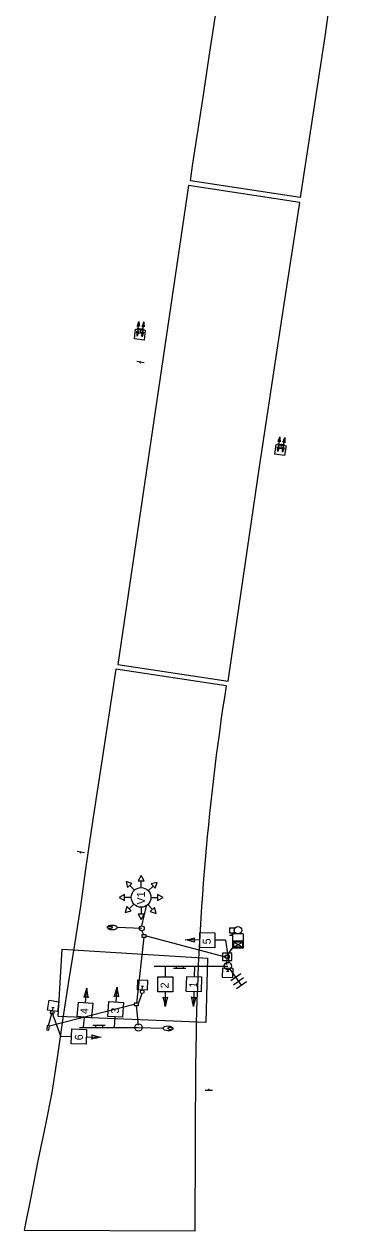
# Model space of a CAD drawing. Extents: x 991933 to 997296, y 1973751 to 1976728.
# Drawn here: x 991933.1 to 992072.6, y 1975023.7 to 1975513.6 of the extents above; entities that cross this region are included whole.
import ezdxf

# ---------------------------------------------------------------- set-up
doc = ezdxf.new("R2010")
doc.units = 0
for name, color, linetype in [('S_CROSS_DRAIN', 7, 'Continuous'), ('S_CURB', 7, 'Continuous'), ('S_DRIVEWAY', 7, 'Continuous'), ('S_DROP_INLET', 7, 'Continuous'), ('S_PARKING', 7, 'Continuous'), ('S_PAVEMENT_CROWN', 7, 'Continuous'), ('S_SIDEWALK', 7, 'Continuous'), ('S_WALL', 7, 'Continuous')]:
    doc.layers.add(name, color=color, linetype=linetype)

msp = doc.modelspace()

# ---------------------------------------------------------------- linework, layer by layer
at = {"layer": 'S_CROSS_DRAIN'}
for p, q in [((991998.77, 1975130.23), (991993.77, 1975130.23)), ((991994.77, 1975131.23), (991994.77, 1975130.23)), ((991997.77, 1975130.23), (991997.77, 1975131.23)), ((991998.77, 1975130.23), (991997.77, 1975130.23)), ((991961, 1975107.29), (991962, 1975107.29)), ((991961, 1975107.29), (991966, 1975107.29)), ((991962, 1975107.29), (991962, 1975106.29)), ((991965, 1975106.29), (991965, 1975107.29))]:
    msp.add_line(p, q, dxfattribs=at)
at = {"layer": 'S_CURB'}
for p, q in [((991981.78, 1975389.65), (991978.8, 1975390)), ((991979.3, 1975389.94), (991978.95, 1975386.94)), ((991979.3, 1975389.94), (991979.65, 1975392.94)), ((991980.14, 1975389.59), (991980.17, 1975389.84)), ((991980.14, 1975389.59), (991980.39, 1975389.56)), ((991980.42, 1975389.81), (991980.17, 1975389.84)), ((991980.42, 1975389.81), (991980.39, 1975389.56)), ((991981.29, 1975389.71), (991980.94, 1975386.71)), ((991981.29, 1975389.71), (991981.63, 1975392.71)), ((991981.75, 1975376.15), (991978.78, 1975376.6)), ((991980.11, 1975376.15), (991980.14, 1975376.39)), ((991980.11, 1975376.15), (991980.35, 1975376.11)), ((991980.39, 1975376.36), (991980.14, 1975376.39)), ((991980.39, 1975376.36), (991980.35, 1975376.11)), ((992036.46, 1975343.08), (992036.88, 1975346.07)), ((992038.44, 1975342.8), (992038.86, 1975345.79)), ((992038.93, 1975342.73), (992035.96, 1975343.15)), ((992036.46, 1975343.08), (992036.03, 1975340.09)), ((992037.29, 1975342.71), (992037.32, 1975342.96)), ((992037.29, 1975342.71), (992037.54, 1975342.68)), ((992037.57, 1975342.92), (992037.32, 1975342.96)), ((992037.57, 1975342.92), (992037.54, 1975342.68)), ((992038.44, 1975342.8), (992038.01, 1975339.81)), ((991957.53, 1975177.26), (991954.57, 1975177.71)), ((991955.89, 1975177.25), (991955.93, 1975177.5)), ((991955.89, 1975177.25), (991956.14, 1975177.22)), ((991956.18, 1975177.46), (991955.93, 1975177.5)), ((991956.18, 1975177.46), (991956.14, 1975177.22)), ((991985.8, 1975131.23), (992015.8, 1975131.23)), ((991955.51, 1975106.29), (991979.51, 1975106.29)), ((992006.57, 1975080.88), (992009.57, 1975080.78)), ((992007.95, 1975080.84), (992007.96, 1975081.09)), ((992007.95, 1975080.84), (992008.2, 1975080.83)), ((992008.21, 1975081.08), (992007.96, 1975081.09)), ((992008.21, 1975081.08), (992008.2, 1975080.83))]:
    msp.add_line(p, q, dxfattribs=at)
for centre, radius in [((991980.85, 1975146.53), 1), ((992015.8, 1975131.23), 1.5), ((991981.02, 1975120.81), 0.75), ((991944.47, 1975112.33), 0.75), ((991979.51, 1975106.29), 1.5)]:
    msp.add_circle(centre, radius, dxfattribs=at)
for centre, radius, start, end in [((991979.26, 1975389.55), 0.814, 231.5757, 295.2703), ((991964.23, 1975386.42), 14.74, 2.0313, 9.7695), ((991993.18, 1975383.08), 14.74, 157.0766, 164.8147), ((991965.42, 1975396.8), 14.74, 337.0766, 344.8147), ((991979.34, 1975390.32), 0.814, 51.5757, 115.2703), ((991994.37, 1975393.46), 14.74, 182.0313, 189.7695), ((991981.24, 1975389.32), 0.814, 231.5757, 295.2703), ((991966.21, 1975386.19), 14.74, 2.0313, 9.7695), ((991995.16, 1975382.85), 14.74, 157.0766, 164.8147), ((991967.41, 1975396.57), 14.74, 337.0766, 344.8147), ((991981.33, 1975390.09), 0.814, 51.5757, 115.2703), ((991996.36, 1975393.23), 14.74, 182.0313, 189.7695), ((992022.77, 1975350.31), 14.74, 335.5548, 343.2929), ((992051.62, 1975346.2), 14.74, 180.5096, 188.2477), ((992024.75, 1975350.03), 14.74, 335.5548, 343.2929), ((992053.6, 1975345.92), 14.74, 180.5096, 188.2477), ((992036.4, 1975342.7), 0.814, 230.0539, 293.7486), ((992021.3, 1975339.96), 14.74, 0.5096, 8.2477), ((992050.15, 1975335.86), 14.74, 155.5548, 163.2929), ((992036.51, 1975343.47), 0.814, 50.0539, 113.7486), ((992038.38, 1975342.42), 0.814, 230.0539, 293.7486), ((992023.28, 1975339.68), 14.74, 0.5096, 8.2477), ((992052.13, 1975335.57), 14.74, 155.5548, 163.2929), ((992038.49, 1975343.18), 0.814, 50.0539, 113.7486)]:
    msp.add_arc(centre, radius, start, end, dxfattribs=at)
at = {"layer": 'S_DRIVEWAY'}
for p, q in [((991980.26, 1975389.58), (991980.11, 1975388.27)), ((991979.68, 1975388.32), (991980.55, 1975388.22)), ((992036.79, 1975341.45), (992037.66, 1975341.33)), ((992037.41, 1975342.69), (992037.23, 1975341.39)), ((991980.82, 1975143.93), (991980.82, 1975143.01)), ((991982.57, 1975143.93), (991980.82, 1975143.93)), ((991982.57, 1975143.01), (991982.57, 1975143.93)), ((991980.82, 1975143.01), (991982.57, 1975143.01)), ((992017.39, 1975136.45), (992013.64, 1975136.45)), ((992013.64, 1975136.45), (992013.64, 1975133.53)), ((992014.64, 1975134.53), (992014.64, 1975135.45)), ((992014.64, 1975135.45), (992016.39, 1975135.45)), ((992014.64, 1975135.45), (992014.64, 1975134.53)), ((992016.39, 1975135.45), (992014.64, 1975135.45)), ((992014.64, 1975134.53), (992016.39, 1975134.53)), ((992014.64, 1975134.53), (992016.39, 1975134.53)), ((992016.39, 1975134.53), (992016.39, 1975135.45)), ((992016.39, 1975134.53), (992016.39, 1975135.45)), ((992017.39, 1975133.53), (992017.39, 1975136.45)), ((992013.64, 1975133.53), (992017.39, 1975133.53)), ((992015.29, 1975129.17), (992016.17, 1975129.15)), ((992015.77, 1975130.48), (992015.73, 1975129.16)), ((991981.52, 1975122.87), (991980.65, 1975122.89)), ((991981.04, 1975121.56), (991981.08, 1975122.88)), ((991945.22, 1975114.3), (991944.36, 1975114.44)), ((991944.58, 1975113.07), (991944.79, 1975114.37)), ((991977.77, 1975116.2), (991977.77, 1975115.28)), ((991979.52, 1975116.2), (991977.77, 1975116.2)), ((991977.77, 1975115.28), (991979.52, 1975115.28)), ((991979.52, 1975115.28), (991979.52, 1975116.2)), ((991942.44, 1975107.11), (991942.22, 1975105.38)), ((991942.22, 1975105.38), (991943.13, 1975105.26)), ((991943.35, 1975107), (991942.44, 1975107.11)), ((991943.13, 1975105.26), (991943.35, 1975107))]:
    msp.add_line(p, q, dxfattribs=at)
at = {"layer": 'S_DROP_INLET'}
for points in [[(991982.25, 1975389.35), (991981.79, 1975385.37), (991977.82, 1975385.83), (991978.28, 1975389.8)], [(992039.39, 1975342.41), (992038.83, 1975338.45), (992034.87, 1975339.02), (992035.43, 1975342.98)], [(992017.77, 1975130.41), (992017.65, 1975126.42), (992013.65, 1975126.54), (992013.77, 1975130.54)], [(991979.04, 1975121.63), (991979.17, 1975125.62), (991983.17, 1975125.5), (991983.04, 1975121.5)], [(991942.61, 1975113.38), (991943.24, 1975117.33), (991947.19, 1975116.7), (991946.56, 1975112.75)]]:
    msp.add_lwpolyline(points, close=True, dxfattribs=at)
at = {"layer": 'S_PARKING'}
for p, q in [((991981.69, 1975143.93), (991980.85, 1975145.53)), ((992016.39, 1975146.77), (992016.39, 1975144.77)), ((992016.39, 1975146.77), (992018.39, 1975146.77)), ((992016.39, 1975144.77), (992018.39, 1975144.77)), ((992016.39, 1975143.77), (992017.39, 1975143.77)), ((992017.39, 1975144.77), (992017.39, 1975143.77)), ((992018.39, 1975146.77), (992018.39, 1975144.77)), ((991981.69, 1975143.01), (991978.65, 1975116.2)), ((991982.57, 1975143.47), (992014.64, 1975134.99)), ((992015.42, 1975131.88), (992015.51, 1975134.53)), ((992015.51, 1975135.45), (992017.73, 1975138.53)), ((991980.82, 1975120.09), (991979.52, 1975116.2)), ((991943.35, 1975107), (991977.77, 1975115.74)), ((991979.51, 1975107.29), (991978.65, 1975115.28)), ((991942.89, 1975107.06), (991944.47, 1975112.33))]:
    msp.add_line(p, q, dxfattribs=at)
msp.add_circle((992019.89, 1975145.77), 1.5, dxfattribs=at)
at = {"layer": 'S_PAVEMENT_CROWN'}
for p, q in [((992017.73, 1975144.27), (992017.73, 1975138.53)), ((992022.06, 1975144.27), (992017.73, 1975144.27)), ((992022.06, 1975144.27), (992022.06, 1975138.53)), ((992022.06, 1975141.27), (992017.73, 1975141.27)), ((992021.73, 1975140.94), (992018.06, 1975140.94)), ((992021.71, 1975138.86), (992018.06, 1975140.94)), ((992018.06, 1975138.86), (992021.73, 1975140.94)), ((992018.06, 1975140.94), (992018.06, 1975138.86)), ((992021.73, 1975138.86), (992018.06, 1975138.86)), ((992021.73, 1975140.94), (992021.73, 1975138.86)), ((992022.06, 1975138.53), (992017.73, 1975138.53))]:
    msp.add_line(p, q, dxfattribs=at)
at = {"layer": 'S_SIDEWALK'}
for p, q in [((991977.81, 1975161.99), (991975.94, 1975163.97)), ((991980.55, 1975163.08), (991980.55, 1975165.8)), ((991983.46, 1975161.83), (991985.44, 1975163.69)), ((991976.55, 1975159.08), (991973.83, 1975159.08)), ((991984.55, 1975159.08), (991987.27, 1975159.08)), ((991977.64, 1975156.34), (991975.66, 1975154.47)), ((991980.55, 1975155.08), (991980.55, 1975152.36)), ((991980.85, 1975147.53), (991982.7, 1975155.71)), ((991983.29, 1975156.17), (991985.16, 1975154.19)), ((991980.85, 1975146.53), (991970.86, 1975146.83)), ((992004.43, 1975141.79), (991998.39, 1975141.86)), ((992014.84, 1975141.69), (992010.49, 1975141.74)), ((992014.84, 1975141.69), (992016.19, 1975132.67)), ((991990.36, 1975131.23), (991990.36, 1975126.88)), ((992002.18, 1975131.23), (992002.07, 1975126.88)), ((992021.33, 1975123.5), (992016.67, 1975130.01)), ((992016.97, 1975125.3), (992021.03, 1975128.21)), ((992018.13, 1975123.67), (992022.19, 1975126.58)), ((992019.29, 1975122.05), (992023.36, 1975124.96)), ((991958, 1975116.37), (991958.49, 1975122.22)), ((991970.4, 1975116.68), (991970.78, 1975122.71)), ((991990.38, 1975120.82), (991990.38, 1975114.78)), ((992001.94, 1975120.82), (992001.79, 1975114.78)), ((991947.93, 1975102.75), (991944.47, 1975112.33)), ((991957.17, 1975106.29), (991957.53, 1975110.5)), ((991969.78, 1975106.29), (991970.05, 1975110.62)), ((991979.51, 1975106.29), (991989.51, 1975105.98)), ((991947.93, 1975102.75), (991952.28, 1975102.63)), ((991958.34, 1975102.49), (991964.38, 1975102.32))]:
    msp.add_line(p, q, dxfattribs=at)
for points in [[(991974.44, 1975165.56), (991975.06, 1975163.14), (991976.83, 1975164.81)], [(991980.55, 1975167.98), (991979.33, 1975165.8), (991981.77, 1975165.8)], [(991987.03, 1975165.19), (991984.6, 1975164.58), (991986.28, 1975162.8)], [(991971.65, 1975159.08), (991973.83, 1975157.86), (991973.83, 1975160.3)], [(991989.45, 1975159.08), (991987.27, 1975160.3), (991987.27, 1975157.86)], [(991974.07, 1975152.98), (991976.5, 1975153.59), (991974.82, 1975155.36)], [(991986.66, 1975152.6), (991986.05, 1975155.03), (991984.27, 1975153.36)], [(991980.55, 1975150.18), (991981.77, 1975152.36), (991979.33, 1975152.36)], [(992010.53, 1975144.76), (992010.45, 1975138.69), (992004.39, 1975138.77), (992004.46, 1975144.83)], [(991987.34, 1975126.88), (991993.4, 1975126.88), (991993.4, 1975120.82), (991987.34, 1975120.82)], [(991999.06, 1975126.96), (992005.12, 1975126.8), (992004.97, 1975120.74), (991998.91, 1975120.89)], [(991960.45, 1975110.25), (991954.57, 1975110.74), (991955.07, 1975116.62), (991960.94, 1975116.12)], [(991973.06, 1975110.44), (991967.01, 1975110.81), (991967.39, 1975116.86), (991973.44, 1975116.49)], [(991952.2, 1975099.62), (991952.36, 1975105.68), (991958.43, 1975105.51), (991958.26, 1975099.45)]]:
    msp.add_lwpolyline(points, close=True, dxfattribs=at)
msp.add_circle((991980.55, 1975159.08), 4, dxfattribs=at)
for centre, radius, start, end in [((991994.33, 1975171.06), 29.47, 277.9152, 285.6533), ((991993.62, 1975112.78), 29.47, 72.9605, 80.6986), ((992003.65, 1975141.8), 1.63, 147.4596, 211.1542), ((991930.62, 1975128.87), 28.65, 338.8586, 346.5967), ((991987.07, 1975124.13), 28.65, 183.8133, 191.5514), ((991941.97, 1975128.92), 29.47, 340.0833, 347.8214), ((991970.45, 1975117.45), 1.63, 54.5824, 118.277), ((992000.14, 1975125.29), 29.47, 185.038, 192.7761), ((991958.06, 1975117.12), 1.58, 53.3577, 117.0523), ((991990.38, 1975120.04), 1.63, 238.1527, 301.8473), ((991961.24, 1975110.36), 29.47, 8.6083, 16.3464), ((992019.52, 1975110.36), 29.47, 163.6536, 171.3917), ((992001.92, 1975120.05), 1.63, 236.7196, 300.4143), ((991972.55, 1975111.1), 29.47, 7.1752, 14.9134), ((992030.81, 1975109.64), 29.47, 162.2205, 169.9586), ((991959.12, 1975102.46), 1.63, 326.5672, 30.2619), ((991967.98, 1975073.07), 29.47, 97.0229, 104.761), ((991969.6, 1975131.33), 29.47, 252.0681, 259.8062)]:
    msp.add_arc(centre, radius, start, end, dxfattribs=at)
for centre, major_axis in [((991968.86, 1975146.89), (-2, 0.06)), ((991967.86, 1975146.92), (1, -0.03)), ((991991.5, 1975105.92), (2, -0.06)), ((991992.5, 1975105.89), (-1, 0.03))]:
    msp.add_ellipse(centre, major_axis=major_axis, ratio=0.5, dxfattribs=at)
at = {"layer": 'S_WALL'}
for p, q in [((992055.11, 1975508.56), (992045.18, 1975443.22)), ((991999.75, 1975448.12), (991971.08, 1975253.7)), ((992044.94, 1975441.23), (991999.75, 1975448.12)), ((992045.18, 1975443.22), (992000.56, 1975450.02)), ((992015.08, 1975244.98), (991970.35, 1975251.79)), ((991971.08, 1975253.7), (992015.93, 1975246.88)), ((991946.89, 1975110.68), (991948.48, 1975138.04)), ((991948.48, 1975138.04), (992007.56, 1975134.45)), ((992007.56, 1975134.45), (992006.9, 1975108.33)), ((992006.9, 1975108.33), (991946.89, 1975110.68)), ((992002.51, 1975023.72), (992002.77, 1975093.76)), ((991933.05, 1975023.95), (992002.51, 1975023.72))]:
    msp.add_line(p, q, dxfattribs=at)
for points in [[(992000.56, 1975450.02), (992001.46, 1975456.11), (992003.72, 1975470.85), (992006.07, 1975485.68), (992008.13, 1975500.54), (992010.43, 1975515.34), (992012.81, 1975530.17), (992015.1, 1975545.07), (992017.26, 1975559.93), (992019.39, 1975574.75), (992021.66, 1975589.56), (992024.03, 1975604.36), (992025.04, 1975610.86), (992026.22, 1975619.18), (992026.22, 1975619.18), (992026.22, 1975619.18), (992026.22, 1975619.18), (992026.22, 1975619.18), (992030.39, 1975646.15), (992030.39, 1975646.15), (992030.39, 1975646.15), (992032.91, 1975663.67)], [(992072.63, 1975621.12), (992065.41, 1975580.76), (992059.93, 1975543.02), (992055.11, 1975508.56)], [(992015.93, 1975246.88), (992017.15, 1975255.28), (992028.62, 1975333.96), (992037.84, 1975394.67), (992044.94, 1975441.23)], [(991970.35, 1975251.79), (991967.27, 1975232.22), (991964.96, 1975217.06), (991962.71, 1975202.23), (991960.29, 1975186.2), (991958.02, 1975170.5), (991955.89, 1975155.59), (991953.45, 1975139.92), (991951.13, 1975124.98), (991948.8, 1975110.04), (991946.59, 1975094.9), (991944.31, 1975079.89), (991941.67, 1975066.87), (991938.68, 1975052.14), (991935.71, 1975037.42), (991933.05, 1975023.95)]]:
    msp.add_lwpolyline(points, dxfattribs=at)
msp.add_arc((993040.91, 1975085.33), 1038.18, 171.15388, 179.53445, dxfattribs=at)

# ---------------------------------------------------------------- texts
at = {"layer": 'S_SIDEWALK'}
for s, height, rotation, p in [('V1', 3.25, 90, (991982.14, 1975156.2)), ('5', 3.25, 89.3069, (992008.82, 1975140.03)), ('2', 3.25, 87.9524, (991991.69, 1975122.09)), ('1', 3.25, 88.411, (992003.35, 1975122.34)), ('3', 3.25, 87.9524, (991971.54, 1975111.89)), ('4', 3.16, 87.9524, (991959.04, 1975111.73)), ('6', 3.25, 88.4145, (991956.85, 1975101.06))]:
    msp.add_text(s, height=height, rotation=rotation, dxfattribs=at).set_placement(p)

doc.saveas('drawing.dxf')
